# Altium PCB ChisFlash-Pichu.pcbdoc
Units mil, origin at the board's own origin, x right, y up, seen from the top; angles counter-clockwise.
Board outline 4828 x 2046.68 mil, 2 copper layers (Top Layer, Bottom Layer); 21 components, 58 nets, 251 pads, 209 vias.
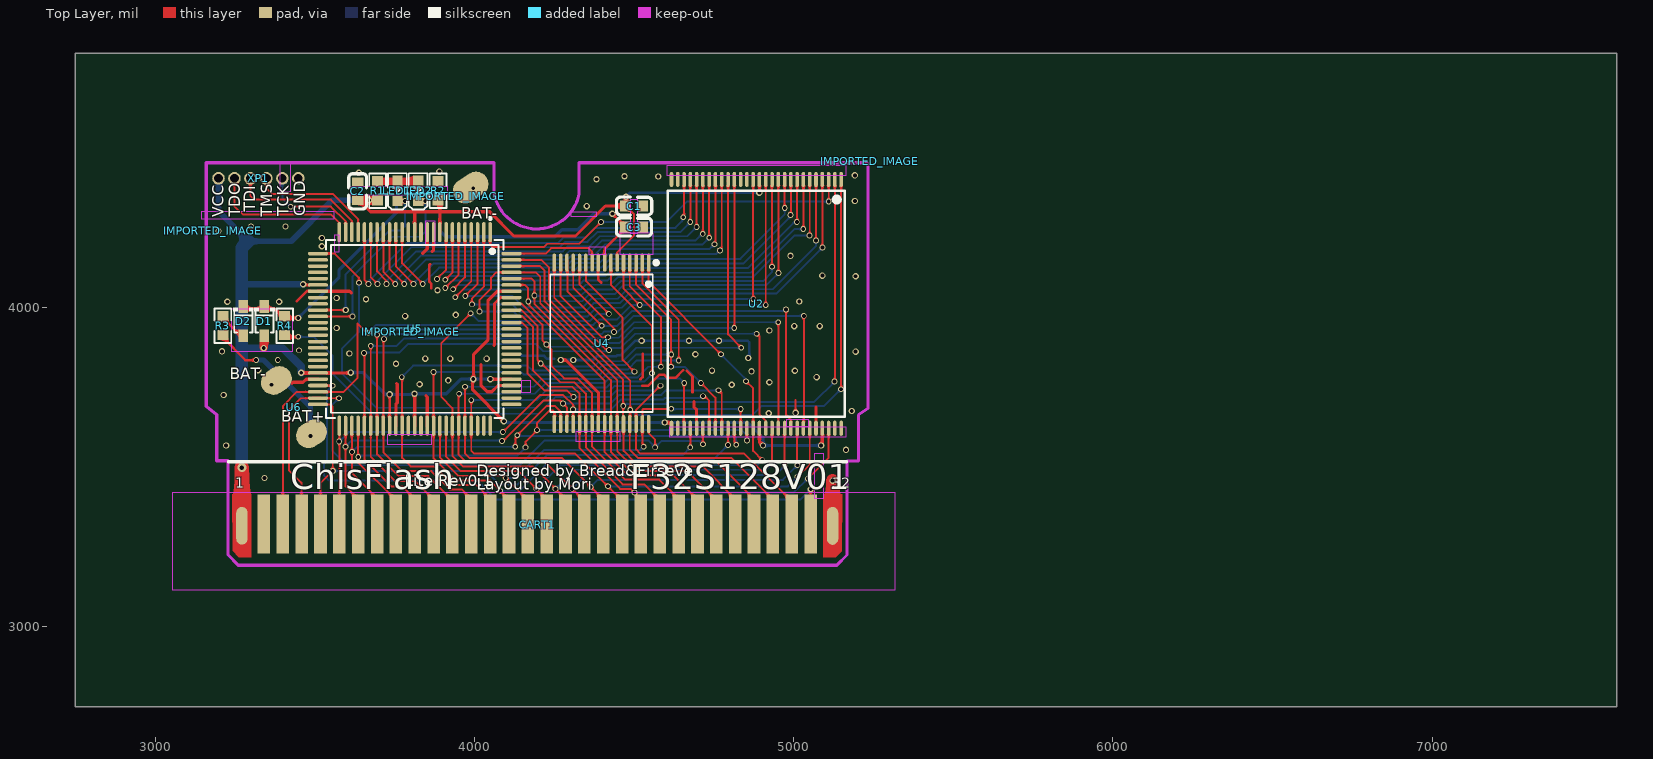
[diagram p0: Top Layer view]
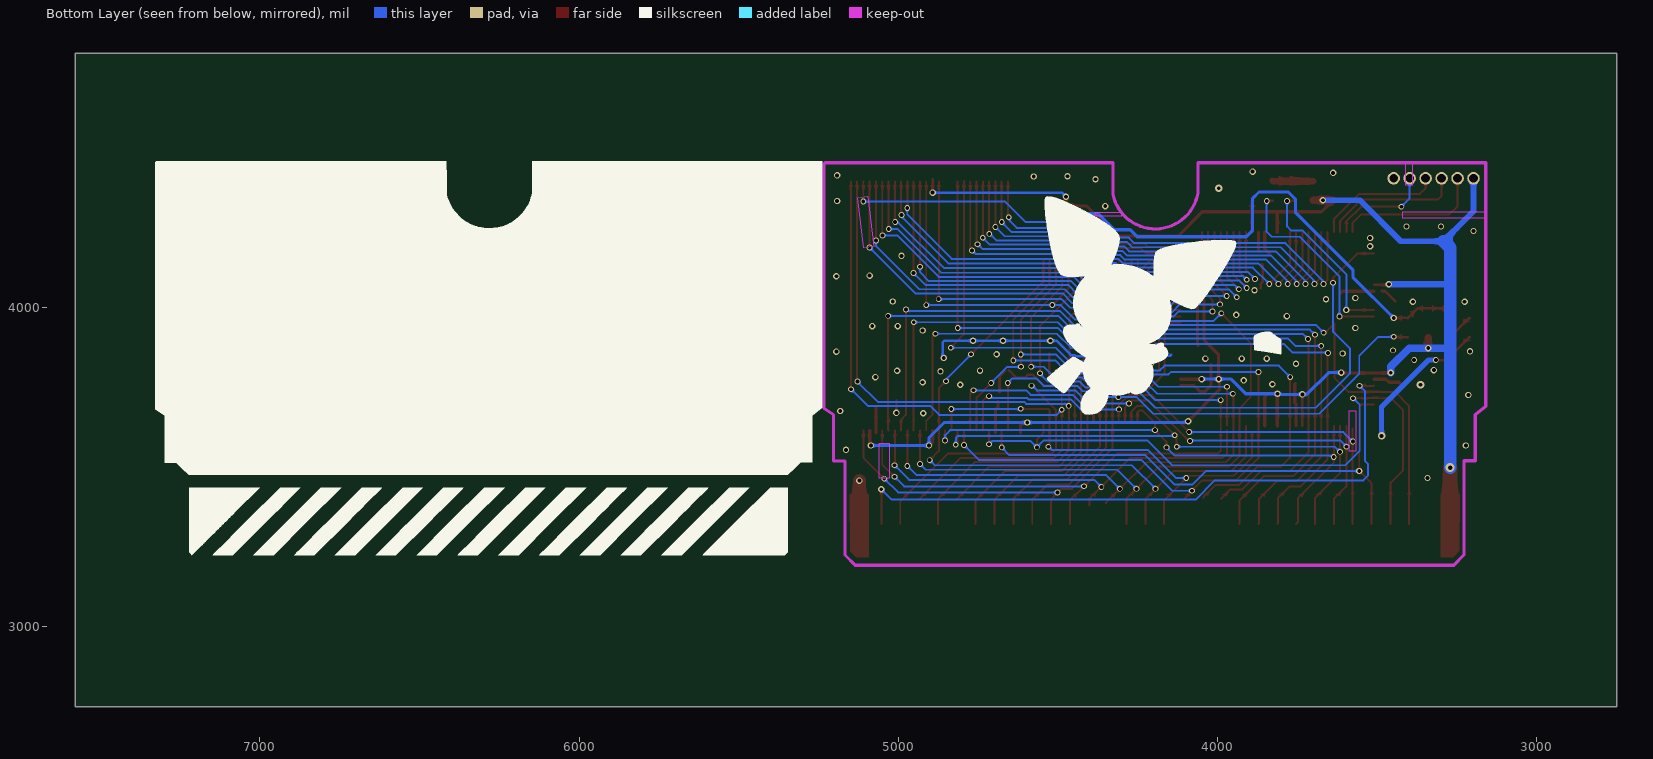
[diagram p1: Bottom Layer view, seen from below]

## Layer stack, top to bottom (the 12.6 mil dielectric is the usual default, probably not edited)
Top Layer: signal copper (thickness not stored)
Dielectric: dielectric 12.6, FR-4, Dk 4.8
Bottom Layer: signal copper (thickness not stored)

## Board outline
7578,2750 2750,2750 2750,4796.68 7578,4796.68

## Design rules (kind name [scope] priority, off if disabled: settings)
Clearance copperThickness1oz [All] p1: gap=7 ignorepadtopadclearanceinfootprint=FALSE except(6: Track-Track Track-SMDPad SMDPad-SMDPad Track-THPad SMDPad-THPad THPad-THPad Track-Via SMDPad-Via THPad-Via Via-Via Track-Fill SMDPad-Fill THPad-Fill Via-Fill Fill-Fill Track-Region SMDPad-Region THPad-Region Via-Region Fill-Region Region-Region Track-Poly SMDPad-Poly THPad-Poly Via-Poly Fill-Poly Region-Poly Poly-Poly Track-Text SMDPad-Text THPad-Text Via-Text Fill-Text Region-Text Poly-Text Text-Text SMDPad-Sheet THPad-Sheet Via-Sheet Fill-Sheet Region-Sheet Poly-Sheet Text-Sheet Track-Hole SMDPad-Hole THPad-Hole Via-Hole Fill-Hole Region-Hole Poly-Hole Text-Hole Sheet-Hole; 11.8: Track-Sheet)
Clearance copperThickness2oz [All] p1: gap=7 ignorepadtopadclearanceinfootprint=FALSE except(6: Track-Track Track-SMDPad SMDPad-SMDPad Track-THPad SMDPad-THPad THPad-THPad Track-Via SMDPad-Via THPad-Via Via-Via Track-Fill SMDPad-Fill THPad-Fill Via-Fill Fill-Fill Track-Region SMDPad-Region THPad-Region Via-Region Fill-Region Region-Region Track-Poly SMDPad-Poly THPad-Poly Via-Poly Fill-Poly Region-Poly Poly-Poly Track-Text SMDPad-Text THPad-Text Via-Text Fill-Text Region-Text Poly-Text Text-Text SMDPad-Sheet THPad-Sheet Via-Sheet Fill-Sheet Region-Sheet Poly-Sheet Text-Sheet Track-Hole SMDPad-Hole THPad-Hole Via-Hole Fill-Hole Region-Hole Poly-Hole Text-Hole Sheet-Hole; 11.8: Track-Sheet)
DiffPairsRouting differentialPair [All] p1: maxuncoupledlength=10 maxlimit=6 mostfreqgap=6 toplayer_minwidth=6 toplayer_prefwidth=10 toplayer_maxwidth=100 bottomlayer_minwidth=6 bottomlayer_prefwidth=10 bottomlayer_maxwidth=100
PasteMaskExpansion pasteMaskExpansion [All] p1:
PlaneConnect innerPlane [All] p1: planeconnectstyle=Relief reliefexpansion=20 reliefentries=4 reliefconductorwidth=10 reliefairgap=10
PolygonConnect copperRegion [All] p1: connectstyle=Direct reliefentries=4 reliefconductorwidth=10 polygonreliefangle="90 Angle" airgapwidth=10
RoutingVias viaSize [All] p1: viastyle="Through Hole" holewidth=12 minholewidth=12 maxholewidth=248 width=20 minwidth=16 maxwidth=393.7
SolderMaskExpansion solderMaskExpansion [All] p1: useseparateexpansions=TRUE expansion=2 expansionbottom=2
Width copperThickness1oz [All] p1: maxlimit=100 minlimit=6 preferedwidth=8
Width copperThickness2oz [All] p1: maxlimit=100 minlimit=6 preferedwidth=10

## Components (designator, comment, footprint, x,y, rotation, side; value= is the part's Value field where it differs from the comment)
C1 "CAP_0603" C0603 4500,4318.68 r180 top
C2 "CAP_0603" C0603 3633.94,4364.68 r270 top
C3 "CGA0603X7R104K500JT" C0603 4500,4252.68 r0 top
CART1 "GBACartridge" GBACartridge 4195.7,3905.83 r0 top
D1 "1N4148WS_C917117" SOD-323_L1.8-W1.3-LS2.5-RD 3342,3957.89 r270 top
D2 "1N4148WS_C917117" SOD-323_L1.8-W1.3-LS2.5-RD 3276,3957.89 r270 top
IMPORTED_IMAGE "IMPORTED_IMAGE" IMPORTED_IMAGE 3180,4240.68 r0 top
IMPORTED_IMAGE "IMPORTED_IMAGE" IMPORTED_IMAGE 3942,4348.68 r0 top
IMPORTED_IMAGE "IMPORTED_IMAGE" IMPORTED_IMAGE 3800,3924.68 r0 top
IMPORTED_IMAGE "IMPORTED_IMAGE" IMPORTED_IMAGE 5238,4458.68 r0 top
LED1 "NCD0603B1" LED0603-RD 3758.38,4366.68 r90 top
LED2 "NCD0603G1" LED0603-RD 3823.78,4366.68 r90 top
R1 "0603WAF1001T5E" R0603 3696.28,4366.68 r270 top
R2 "0603WAF1003T5E" R0603 3885.94,4366.68 r90 top
R3 "0603WAF1002T5E" R0603 3212,3943.84 r90 top
R4 "0603WAF1002T5E" R0603 3405.35,3943.84 r90 top
U2 "S29GL256S10TFI010" TSOP-56_L18.4-W14.0-P0.50-LS20.0-TL 4883,4012.43 r270 top
U4 "={Manufacturer Part}" STSOP-32_L8.0-W11.8-P0.50-LS13.4-TL 4398,3888.51 r270 top
U5 "EPM240T100C5N" TQFP-100_L14.0-W14.0-P0.50-LS16.0-BL 3812.79,3933.68 r180 top
U6 "+电池-" 电池 3379.43,3772.2 r303.35 top
XP1 "jtag" HDR-TH_6P-P1.27-V-M-1 3323,4405.68 r0 top

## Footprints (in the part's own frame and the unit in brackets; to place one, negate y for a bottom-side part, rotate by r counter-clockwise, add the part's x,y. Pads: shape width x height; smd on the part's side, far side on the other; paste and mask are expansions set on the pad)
C0603 [mm]
  rect 0.8x0.9 smd: 1(-0.7,0) 2(0.7,0)
  silkscreen extent -1.41,-0.71 1.39,0.72
GBACartridge [mm]
  oval 0.905x2.997 smd: 1(-23.479,-14.958)
  rect 1x4.691 smd: 2(-21.724,-14.805) 3(-20.224,-14.805) 4(-18.724,-14.805) 5(-17.224,-14.805) 6(-15.724,-14.805) 7(-14.224,-14.805) 8(-12.724,-14.805) 9(-11.224,-14.805) 10(-9.724,-14.805) 11(-8.224,-14.805) 12(-6.724,-14.805) 13(-5.224,-14.805) 14(-3.724,-14.805) 15(-2.224,-14.805) 16(-0.724,-14.805) 17(0.776,-14.805) 18(2.276,-14.805) 19(3.776,-14.805) 20(5.276,-14.805) 21(6.776,-14.805) 22(8.276,-14.805) 23(9.776,-14.805) 24(11.276,-14.805) 25(12.776,-14.805) 26(14.276,-14.805) 27(15.776,-14.805) 28(17.276,-14.805) 29(18.776,-14.805) 30(20.276,-14.805) 31(21.776,-14.805)
  oval 0.904x3.008 smd: 32(23.529,-14.966)
  Top Layer region: 22.775,-17.473 22.782,-12.46 24.282,-12.46 24.275,-16.973 23.775,-17.473
  Top Layer region: -22.733,-12.46 -22.725,-17.456 -23.725,-17.456 -24.224,-16.956 -24.233,-12.46
HDR-TH_6P-P1.27-V-M-1 [mm]
  round 1 hole 0.7: 1(-3.175,0) 2(-1.905,0) 3(-0.635,0) 4(0.635,0) 5(1.905,0) 6(3.175,0)
IMPORTED_IMAGE [mil]
LED0603-RD [mm]
  rect 0.8x0.8 smd: 1(-0.799,0) 2(0.799,0)
  silkscreen extent -1.49,-0.75 1.39,0.76
R0603 [mil]
  rect 31.75x34.02 smd: 1(-29.66,0) 2(29.66,0)
  silkscreen extent -55,-26 55,26
SOD-323_L1.8-W1.3-LS2.5-RD [mm]
  rect 1x0.75 smd: 1(-1.173,0) 2(1.173,0)
  silkscreen extent -1.08,-0.8 0.9,0.8
STSOP-32_L8.0-W11.8-P0.50-LS13.4-TL [mm]
  oval 1.44x0.28 smd: 1(-6.42,3.75) 2(-6.42,3.25) 3(-6.42,2.75) 4(-6.42,2.25) 5(-6.42,1.75) 6(-6.42,1.25) 7(-6.42,0.75) 8(-6.42,0.25) 9(-6.42,-0.25) 10(-6.42,-0.75) 11(-6.42,-1.25) 12(-6.42,-1.75) 13(-6.42,-2.25) 14(-6.42,-2.75) 15(-6.42,-3.25) 16(-6.42,-3.75) 17(6.42,-3.75) 18(6.42,-3.25) 19(6.42,-2.75) 20(6.42,-2.25) 21(6.42,-1.75) 22(6.42,-1.25) 23(6.42,-0.75) 24(6.42,-0.25) 25(6.42,0.25) 26(6.42,0.75) 27(6.42,1.25) 28(6.42,1.75) 29(6.42,2.25) 30(6.42,2.75) 31(6.42,3.25) 32(6.42,3.75)
  silkscreen extent -6.57,-4.08 5.47,4.49
TQFP-100_L14.0-W14.0-P0.50-LS16.0-BL [mm]
  oval 0.28x1.6 smd: 1(-6,-7.7) 2(-5.5,-7.7) 3(-5,-7.7) 4(-4.5,-7.7) 5(-4,-7.7) 6(-3.5,-7.7) 7(-3,-7.7) 8(-2.5,-7.7) 9(-2,-7.7) 10(-1.5,-7.7) 11(-1,-7.7) 12(-0.5,-7.7) 13(0,-7.7) 14(0.5,-7.7) 15(1,-7.7) 16(1.5,-7.7) 17(2,-7.7) 18(2.5,-7.7) 19(3,-7.7) 20(3.5,-7.7) 21(4,-7.7) 22(4.5,-7.7) 23(5,-7.7) 24(5.5,-7.7) 25(6,-7.7) 51(6,7.7) 52(5.5,7.7) 53(5,7.7) 54(4.5,7.7) 55(4,7.7) 56(3.5,7.7) 57(3,7.7) 58(2.5,7.7) 59(2,7.7) 60(1.5,7.7) 61(1,7.7) 62(0.5,7.7) 63(0,7.7) 64(-0.5,7.7) 65(-1,7.7) 66(-1.5,7.7) 67(-2,7.7) 68(-2.5,7.7) 69(-3,7.7) 70(-3.5,7.7) 71(-4,7.7) 72(-4.5,7.7) 73(-5,7.7) 74(-5.5,7.7) 75(-6,7.7)
  oval 1.6x0.28 smd: 26(7.7,-6) 27(7.7,-5.5) 28(7.7,-5) 29(7.7,-4.5) 30(7.7,-4) 31(7.7,-3.5) 32(7.7,-3) 33(7.7,-2.5) 34(7.7,-2) 35(7.7,-1.5) 36(7.7,-1) 37(7.7,-0.5) 38(7.7,0) 39(7.7,0.5) 40(7.7,1) 41(7.7,1.5) 42(7.7,2) 43(7.7,2.5) 44(7.7,3) 45(7.7,3.5) 46(7.7,4) 47(7.7,4.5) 48(7.7,5) 49(7.7,5.5) 50(7.7,6) 76(-7.7,6) 77(-7.7,5.5) 78(-7.7,5) 79(-7.7,4.5) 80(-7.7,4) 81(-7.7,3.5) 82(-7.7,3) 83(-7.7,2.5) 84(-7.7,2) 85(-7.7,1.5) 86(-7.7,1) 87(-7.7,0.5) 88(-7.7,0) 89(-7.7,-0.5) 90(-7.7,-1) 91(-7.7,-1.5) 92(-7.7,-2) 93(-7.7,-2.5) 94(-7.7,-3) 95(-7.7,-3.5) 96(-7.7,-4) 97(-7.7,-4.5) 98(-7.7,-5) 99(-7.7,-5.5) 100(-7.7,-6)
  silkscreen extent -7.08,-8.9 7.08,7.08
TSOP-56_L18.4-W14.0-P0.50-LS20.0-TL [mil]
  oval 47.2x11 smd: 1(-389.8,265.8) 2(-389.8,246.1) 3(-389.8,226.4) 4(-389.8,206.7) 5(-389.8,187) 6(-389.8,167.3) 7(-389.8,147.6) 8(-389.8,128) 9(-389.8,108.3) 10(-389.8,88.6) 11(-389.8,68.9) 12(-389.8,49.2) 13(-389.8,29.5) 14(-389.8,9.8) 15(-389.8,-9.8) 16(-389.8,-29.5) 17(-389.8,-49.2) 18(-389.8,-68.9) 19(-389.8,-88.6) 20(-389.8,-108.3) 21(-389.8,-127.9) 22(-389.8,-147.6) 23(-389.8,-167.3) 24(-389.8,-187) 25(-389.8,-206.7) 26(-389.8,-226.4) 27(-389.8,-246.1) 28(-389.8,-265.7) 29(389.8,-265.7) 30(389.8,-246.1) 31(389.8,-226.4) 32(389.8,-206.7) 33(389.8,-187) 34(389.8,-167.3) 35(389.8,-147.6) 36(389.8,-127.9) 37(389.8,-108.3) 38(389.8,-88.6) 39(389.8,-68.9) 40(389.8,-49.2) 41(389.8,-29.5) 42(389.8,-9.8) 43(389.8,9.8) 44(389.8,29.5) 45(389.8,49.2) 46(389.8,68.9) 47(389.8,88.6) 48(389.8,108.3) 49(389.8,128) 50(389.8,147.6) 51(389.8,167.3) 52(389.8,187) 53(389.8,206.7) 54(389.8,226.4) 55(389.8,246.1) 56(389.8,265.8)
  silkscreen extent -354,-278 354,278
电池 [mm]
  oval 2x2.54 smd: 1(0,0) 2(5.08,0)

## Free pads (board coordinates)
  oval 118.11x78.74 smd rot 33.35: 2(3988,4376.68)

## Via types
v1: diameter 18, hole 12, Top Layer to Bottom Layer, 125 vias
v2: diameter 20, hole 12, Top Layer to Bottom Layer, 80 vias
v3: diameter 24, hole 12, Top Layer to Bottom Layer, 3 vias
v4: diameter 28, hole 14, Top Layer to Bottom Layer, 1 vias

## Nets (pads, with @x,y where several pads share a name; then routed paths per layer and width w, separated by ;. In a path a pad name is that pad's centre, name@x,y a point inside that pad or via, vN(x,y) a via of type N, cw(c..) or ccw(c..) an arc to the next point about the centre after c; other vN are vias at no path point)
$1N77583: LED1.2 LED2.2 R1.1 | length 128.2
  Top Layer w20: R1.1@3700.28,4396.34 3825.96,4396.34 LED2.2@3827.78,4398.15
$1N81263: D2.2 R3.2 | length 89.6
  Top Layer w8: R3.2@3210,3967.5 3212.23,3967.5 D2.2@3274,3905.73
$1N81264: R3.1 U6.2 | length 458.1
  Top Layer w8: R3.1@3210,3908.18 3282.53,3835.65 3314.97,3835.65 v1(3316,3836.68)
  Bottom Layer w16: v1(3316,3836.68) 3338.63,3836.68 3486,3689.3 v3(3486,3598.68)
A16: CART1.22 U2.54 U4.21 U5.90 | length 1638.8
  Top Layer w6: U5.90 4149.63,3973.05 4184,3938.68 4184,3802.68 4234,3752.68 4306.37,3752.68 4329.1,3729.94 4329.1,3640.91 4329.1,3559.86 4456.29,3432.68 4490.2,3432.68 v1(4501.46,3421.42) 4501.46,3420.58 4521.51,3400.53 CART1.22 ; v1(5044,3464.68) 5109.4,3530.08 U2.54@5109.4,3615.88
  Bottom Layer w6: v1(4501.46,3421.42) 5000.74,3421.42 v1(5044,3464.68)
A17: CART1.23 U2.19 U4.22 U5.91 | length 2146
  Top Layer w6: U5.91 4147.94,3992.74 4198,3942.68 4198,3835.62 v1(4207.8,3825.82) 4208.94,3825.82 4268.08,3766.68 4313.24,3766.68 4348.79,3731.12 4348.79,3636.91 4348.79,3562.31 4464.19,3446.91 4532.49,3446.91 4580.56,3398.84 CART1.23 ; U2.19@4792,4397.88 4794.33,4395.55 4794.33,3916.35 v1(4836,3874.68)
  Bottom Layer w6: v1(4207.8,3825.82) 4217.47,3816.15 4374.89,3816.15 4391.13,3832.39 4464,3832.39 4506.28,3874.68 v1(4836,3874.68)
A18: CART1.24 U2.18 U4.23 U5.92 | length 2085.9
  Top Layer w6: U5.92 4116.2,4012.68 4148,4012.68 4213.06,3947.61 4213.06,3897.61 v1(4226,3884.68) 4242,3868.68 4242,3817.5 4280.82,3778.68 4321.41,3778.68 4368.47,3731.61 4368.47,3636.91 4368.47,3565.14 4472.15,3461.46 4579.21,3461.46 4639.62,3401.06 CART1.24 ; v1(4814,3936.68) 4814.1,3936.78 U2.18@4814.1,4395.48
  Bottom Layer w6: v1(4226,3884.68) 4232.64,3878.04 4401.34,3878.04 4412.82,3889.52 4454.19,3889.52 4501.35,3936.68 v1(4814,3936.68)
A19: CART1.25 U2.11 U4.25 U5.95 | length 2206.2
  Top Layer w6: U5.95 4157.32,4071.48 4168.23,4060.57 v1(4168.23,4019.71) 4168.23,4011.73 4407.84,3772.11 U4.25 4407.84,3547.43 4480.12,3475.15 4623.53,3475.15 4698.67,3400 CART1.25 ; U2.11@4951.9,4395.48 4952.23,4395.15 v1(4952.23,4108.93)
  Bottom Layer w6: v1(4168.23,4019.71) 4168.9,4020.38 4337.05,4020.38 4359.61,4042.95 4439.54,4042.95 4467.99,4071.4 4915.37,4071.4 4952.23,4108.25 v1(4952.23,4108.93)
A20: CART1.26 U2.12 U4.26 U5.96 | length 2235.8
  Top Layer w6: U5.96 4179.52,4091.16 4187.66,4083.01 v1(4187.66,4038.78) 4187.66,4013.01 4427.53,3773.14 U4.26 4427.53,3548.56 4487.25,3488.84 4665.84,3488.84 4757.73,3396.95 CART1.26 ; v1(4932,4128.68) 4932,4395.28 U2.12@4932.2,4395.48
  Bottom Layer w6: v1(4187.66,4038.78) 4189.24,4037.2 4333.32,4037.2 4353.32,4057.21 4432.29,4057.21 4458.51,4083.43 4903.97,4083.43 4932,4111.46 v1(4932,4128.68)
A21: CART1.27 U2.15 U4.27 U5.97 | length 2624.1
  Top Layer w6: v1(4016,3988.68) 4016,4024.68 4052,4060.68 4052,4094.68 4068.17,4110.85 U5.97 4191.83,4110.85 4206,4096.68 4206,4013.88 4447.21,3772.67 4447.21,3636.91 4447.21,3550.71 4495.1,3502.82 4714.51,3502.82 CART1.27@4819.16,3398.17 ; U2.15@4873.2,4395.48 4873.2,4027.63 v1(4873.75,4027.09)
  Bottom Layer w6: v1(4016,3988.68) 4122,3988.68 4138.21,3972.46 4353.5,3972.46 4381.21,4000.17 4461.35,4000.17 4488.22,4027.05 v1@4873.71,4027.05
A22: CART1.28 U2.2 U4.28 U5.98 | length 2647.1
  Top Layer w6: U5.98 4206.15,4130.53 4220,4116.68 4220,4020.13 4465.91,3774.22 4465.91,3692.68 4465.91,3641.9 4466.9,3640.91 4466.9,3551.64 4501.91,3516.64 4760.04,3516.64 4875.84,3400.84 CART1.28 ; v1(5128,3768.68) 5129.1,3769.78 U2.2@5129.1,4395.48
  Bottom Layer w6: v1(4466,3692.68) 4472.23,3698.9 4599.69,3698.9 4605.69,3704.9 5064.23,3704.9 v1(5128,3768.68)
A23: CART1.29 U2.1 U4.29 U5.99 | length 2668.3
  Top Layer w6: U5.99 4208.46,4150.22 4234,4124.68 4234,4025.88 4488,3771.88 v1(4488,3680.68) 4488,3642.33 4486.58,3640.91 4486.58,3554.64 4511.73,3529.49 4805.18,3529.49 CART1.29@4935.25,3399.42 ; v1(5148,3744.68) 5148.8,3745.48 U2.1@5148.8,4395.48
  Bottom Layer w6: v1(4488,3680.68) 4504,3664.68 4872,3664.68 4899.73,3692.4 5095.73,3692.4 v1(5148,3744.68)
AD0: CART1.6 U2.35 U4.20 U5.51 | length 1701.7
  Top Layer w6: CART1.6 U5.51@3576.63,3622.53 ; v1(4088.98,3610.6) 4205.05,3726.68 4278.06,3726.68 4308.86,3695.87 v1(4308.86,3681.81) 4309.42,3681.25 U4.20@4309.42,3642.91 ; v1(4716.26,3723.12) 4721.56,3723.12 4735.4,3709.28 U2.35@4735.4,3615.88
  Bottom Layer w6: v1(3576,3580.68) 3605.58,3610.26 4088.63,3610.26 v1(4088.98,3610.6) ; v1(4308.86,3681.81) 4429.05,3681.81 4460.25,3713.01 4592.3,3713.01 4596.55,3717.4 4710.54,3717.4 v1(4716.26,3723.12)
AD1: CART1.7 U2.37 U4.19 U5.52 | length 1768.2
  Top Layer w6: U5.52@3596.27,3630.5 3596,3630.23 v1(3596,3564.68) 3596,3440.68 3635.68,3401 CART1.7 ; v1(4086,3582.68) 4090,3582.68 4217.28,3709.96 4267.56,3709.96 v1(4277.09,3700.43) 4289.73,3687.79 U4.19@4289.73,3642.91 ; v1(4764.89,3741.46) 4774.7,3731.65 U2.37@4774.7,3615.88
  Bottom Layer w6: v1(3596,3564.68) 3616,3584.68 4084,3584.68 v1(4086,3582.68) ; v1(4277.09,3700.43) 4426.34,3700.43 4453.16,3727.25 4585.51,3727.25 4599.72,3741.46 v1(4764.89,3741.46)
AD2: CART1.8 U2.39 U4.18 U5.53 | length 1869.4
  Top Layer w6: U5.53 3615.94,3548.68 3615.94,3482.74 3694.74,3403.94 CART1.8 ; v1(4128,3564.68) 4128,3594.68 v1(4134,3600.68) 4226,3692.68 4251.49,3692.68 4270.05,3674.11 U4.18@4270.05,3642.91 ; U2.39@4814.1,3615.88 4814.1,3576.58 v1(4820,3570.68)
  Bottom Layer w6: v1(3616,3548.68) 3632,3564.68 v1(4128,3564.68) ; v1(4134,3600.68) 4136,3598.68 4814,3598.68 4820,3592.68 v1(4820,3570.68)
AD3: CART1.9 U2.41 U4.17 U5.54 | length 1802.2
  Top Layer w6: U5.54 3635.62,3533.06 v1(3636,3532.68) 3636,3514.68 3748,3402.68 3748,3328.73 CART1.9 ; v1(4160,3562.68) 4160,3580.68 v1(4196,3616.68) 4196,3639.05 4235.62,3678.68 4246,3678.68 4250.36,3674.31 U4.17@4250.36,3640.91 ; v1(4853.55,3584.51) U2.41@4853.55,3615.83
  Bottom Layer w6: v1(3636,3532.68) 3640,3536.68 4134,3536.68 v1(4160,3562.68) ; v1(4196,3616.68) 4838,3616.68 4853.55,3601.13 v1(4853.55,3584.51)
AD4: CART1.10 U2.44 U4.16 U5.55 | length 2566.3
  Top Layer w6: v1(3654,3858.68) 3655.31,3857.37 U5.55 3655.31,3524.98 3739.61,3440.68 3774,3440.68 3810,3404.68 3810,3325.79 CART1.10 ; U4.16@4250,4148.8 4250,4031.4 4413.37,3868.03 v1(4421.15,3868.03) ; v1(4884,3918.68) 4893.46,3909.22 4893.46,3665.22 4912.5,3646.18 U2.44@4912.5,3615.88
  Bottom Layer w6: v1(3654,3858.68) 3655,3859.68 3765,3859.68 3792,3886.68 4192.7,3886.68 4215.51,3863.87 4416.99,3863.87 v1(4421.15,3868.03) 4427.15,3874.03 4458.85,3874.03 4503.49,3918.68 v1(4884,3918.68)
AD5: CART1.11 U2.46 U4.15 U5.56 | length 2637.7
  Top Layer w6: v1(3675.18,3880.7) 3675.15,3630.7 U5.56 3674.99,3532.6 3751.1,3456.48 3815.07,3456.48 3870,3401.56 3870,3324.84 CART1.11 ; U4.15@4269.99,4148.39 4269.99,4036.56 4398.75,3907.8 v1(4418.1,3907.78) ; U2.46@4951.9,3615.88 4951.9,3845.07 4952,3845.16 v1(4952,3954.68)
  Bottom Layer w6: v1(3675.18,3880.7) 3756.1,3880.7 3778.73,3903.33 4413.64,3903.33 v1(4418.1,3907.78) 4419.67,3906.21 4451.78,3906.21 4500.25,3954.68 v1(4952,3954.68)
AD6: CART1.12 U2.48 U4.14 U5.57 | length 2696.8
  Top Layer w6: v1(3694.51,3915.47) 3694.68,3915.3 U5.57 3694.68,3540.96 3763.18,3472.46 3855.35,3472.46 3930.96,3396.85 CART1.12 ; U4.14@4288,4150.17 4292,4146.17 4292,4050.46 v1(4399,3943.46) ; v1(4976.34,3994.68) 4976.34,3664.34 4991.3,3649.38 U2.48@4991.3,3615.88
  Bottom Layer w6: v1(3694.51,3915.47) 3710.72,3931.68 4382.22,3931.68 4394,3943.46 v1(4399,3943.46) 4447.14,3943.46 4493.03,3989.35 4971.01,3989.35 v1(4976.34,3994.68)
AD7: CART1.13 U2.50 U4.13 U5.58 | length 2674.4
  Top Layer w6: v1(3716.53,3902.47) 3714.36,3900.3 U5.58 3714.36,3547.73 3773.84,3488.25 3865.03,3488.25 3922.02,3431.25 3959.77,3431.25 CART1.13@3989.02,3402 ; U4.13@4309.42,4148.43 4309.42,4062.72 4437.33,3934.82 v1(4437.33,3924.16) ; U2.50@5030.6,3615.88 5032,3617.28 v1(5032,3974.68)
  Bottom Layer w6: v1(3716.53,3902.47) 3731.9,3917.84 4398.75,3917.84 4407.15,3926.23 4435.26,3926.23 v1(4437.33,3924.16) 4448.91,3924.16 4499.42,3974.68 v1(5032,3974.68)
AD8: CART1.14 U2.36 U4.3 U5.61 | length 2124.6
  Top Layer w6: v1(3772,3782.68) 3773.42,3781.26 U5.61 3773.42,3529.67 3799.91,3503.18 3874.44,3503.18 3932.48,3445.14 4005.84,3445.14 4043.69,3407.29 CART1.14@4043.69,3404.56 ; U4.3@4506.27,4148.43 4506.27,4072.4 4616.36,3962.31 v1(4616.36,3853.99) 4615.66,3853.29 v1(4615.66,3815) ; v1(4709.23,3764.4) 4755.1,3718.54 U2.36@4755.1,3615.88
  Bottom Layer w6: v1(3772,3782.68) 3808,3818.68 4166,3818.68 4180.53,3804.15 4384.07,3804.15 4400.11,3820.19 4472.95,3820.19 4506.75,3853.99 v1(4616.36,3853.99) ; v1(4615.66,3815) 4658.64,3815 v1(4709.23,3764.4)
AD9: CART1.15 U2.38 U4.2 U5.66 | length 2526.7
  Top Layer w6: v1(3872,3798.68) 3871.84,3798.51 U5.66 3871.84,3528.29 3940.78,3459.35 4047.33,3459.35 v1(4080,3426.68) 4104.91,3401.77 CART1.15@4104.91,3400.65 ; U4.2@4526,4148.39 4526,4076.68 4640.08,3962.6 v1(4640.08,3835.14) ; v1(4794.12,3569.77) 4794.4,3570.05 U2.38@4794.4,3615.88
  Bottom Layer w6: v1(3872,3798.68) 4145.96,3798.68 4153.65,3790.99 4394.37,3790.99 4410.36,3806.98 4481.03,3806.98 4509.2,3835.14 v1(4640.08,3835.14) ; v1(4080,3426.68) 4142,3426.68 4238,3522.68 4747.03,3522.68 v1(4794.12,3569.77)
AD10: 
AD11: CART1.17 U2.42 U4.1 U5.68 | length 2061.2
  Top Layer w6: U5.68 3911.21,3533.78 3956.74,3488.25 4138.43,3488.25 v1(4194,3432.68) 4226.23,3400.44 CART1.17 ; U4.1@4545.64,4146.43 4545.64,4081.03 v1(4772,3854.68) ; v1(4850.68,3770.05) 4873.2,3747.53 U2.42 4873.2,3551.48 v1(4902,3522.68)
  Bottom Layer w6: v1(4194,3432.68) 4268,3506.68 4886,3506.68 v1(4902,3522.68) ; v1(4772,3854.68) 4850.68,3776 v1(4850.68,3770.05)
AD12: CART1.18 U2.45 U4.12 U5.69 | length 2458.3
  Top Layer w6: v1(3988,3982.68) 3930.9,3925.57 3930.9,3923.57 3896,3888.68 3896,3720.68 3930.9,3685.78 U5.69 3930.9,3537.03 3965.27,3502.65 4184.03,3502.65 v1(4254,3432.68) 4285.29,3401.39 CART1.18 ; U4.12@4329.1,4146.43 4329.1,4072.77 v1(4420.96,3980.91) ; v1(4932,3510.68) 4932.2,3510.88 U2.45@4932.2,3615.88
  Bottom Layer w6: v1(3988,3982.68) 4011.79,3958.89 4362.8,3958.89 4384.82,3980.91 v1(4420.96,3980.91) ; v1(4254,3432.68) 4314,3492.68 4914,3492.68 v1(4932,3510.68)
AD13: CART1.19 U2.47 U4.4 U5.70 | length 2500.7
  Top Layer w6: v1(3952,3730.68) 3950.58,3729.25 U5.70 3950.58,3539.83 3974.23,3516.17 4222.51,3516.17 v1(4306,3432.68) 4349.83,3388.85 CART1.19@4349.83,3386.95 ; U4.4@4486.58,4146.43 4486.58,4068.09 4583.92,3970.75 v1(4583.92,3815.33) ; U2.47@4971.6,3615.88 4971.6,3505.08 v1(4972,3504.68)
  Bottom Layer w6: v1(3952,3730.68) 4189.13,3730.68 4222.74,3764.29 4406.87,3764.29 4423.86,3781.27 4510.14,3781.27 4544.19,3815.33 v1(4583.92,3815.33) ; v1(4306,3432.68) 4350,3476.68 4944,3476.68 v1(4972,3504.68)
AD14: CART1.20 U2.49 U4.11 U5.71 | length 2450
  Top Layer w6: v1(3970,3752.68) 3970.27,3752.41 U5.71 ; U5.71@3970.74,3615.09 3970.74,3543.32 3984.41,3529.65 4273.03,3529.65 v1(4364,3438.68) 4401.24,3401.43 CART1.20@4401.24,3380.81 ; U4.11@4348.79,4146.43 4350,4145.23 4350,4083 4464,3969 4464,3837.04 v1(4501.13,3799.92) ; U2.49@5011,3615.88 5011,3507.68 v1(5012,3506.68)
  Bottom Layer w6: v1(3970,3752.68) 4185.84,3752.68 4210.35,3777.19 4400.28,3777.19 4416.56,3793.47 4494.68,3793.47 v1(4501.13,3799.92) ; v1(4364,3438.68) 4386,3460.68 4966,3460.68 v1(5012,3506.68)
AD15: CART1.21 U2.51 U4.7 U5.72 | length 2543.6
  Top Layer w6: v1@3989.95,3710.62 U5.72 3989.95,3552.31 3999.26,3543 4315.67,3543 v1(4418,3440.68) 4462.45,3396.22 CART1.21 ; U4.7@4427.53,4146.43 4427.53,4071.57 4556.25,3942.86 v1(4556.25,3794.93) ; v1(5012,3470.68) 5050.3,3508.98 U2.51@5050.3,3615.88
  Bottom Layer w6: v1(3990,3710.68) 4194.93,3710.68 4234.93,3750.68 4414,3750.68 4432.17,3768.85 4532.49,3768.85 4556.25,3792.61 v1(4556.25,3794.93) ; v1(4418,3440.68) 4982,3440.68 v1(5012,3470.68)
BK: U4.10 U5.100 | length 293.6
  Top Layer w6: U5.100 4223.22,4169.9 4240,4186.68 4358,4186.68 4368,4176.68 4368,4146.91 U4.10@4368.47,4146.43
FA0: U2.31 U5.26 | length 1792.5
  Top Layer w6: U5.26 3562.78,4169.9 3638,4094.68 v1(3638,4078.68) ; U2.31@4656.17,3615.45 4656.17,3763.5 v1(4657.01,3764.34)
  Bottom Layer w6: v1(3638,4078.68) 3638,3924.68 3584.54,3871.22 3584.54,3794.18 3692.04,3686.68 4195.69,3686.68 4247.61,3738.6 4421.92,3738.6 4438.85,3755.53 4544.96,3755.53 4568.11,3778.68 4642.68,3778.68 v1(4657.01,3764.34)
FA1: U2.26 U5.21 | length 1363
  Top Layer w6: U5.21 3655.31,4087.37 v1(3668,4074.68) ; v1(4654.18,4283.56) 4656.6,4285.98 U2.26@4656.6,4395.48
  Bottom Layer w6: v1(3668,4074.68) 3668,4083.16 3787.39,4202.55 4260.44,4202.55 4277.54,4219.65 4346.43,4219.65 4376.99,4250.21 4629.32,4250.21 4654.18,4275.07 v1(4654.18,4283.56)
FA2: U2.25 U5.20 | length 1363.1
  Top Layer w6: U5.20 3674.99,4095.69 v1(3696,4074.68) ; v1(4675.86,4268.48) 4676.3,4268.92 U2.25@4676.3,4395.48
  Bottom Layer w6: v1(3696,4074.68) 3696,4083.16 3802.39,4189.55 4267.31,4189.55 4284.08,4206.32 4353.99,4206.32 4384.75,4237.08 4644.29,4237.08 4675.69,4268.48 v1(4675.86,4268.48)
FA3: U2.24 U5.19 | length 1367.4
  Top Layer w6: U5.19 3694.68,4114 3724,4084.68 v1(3724,4074.68) ; v1(4696.01,4253.3) U2.24@4696,4395.48
  Bottom Layer w6: v1(3724,4074.68) 3724,4083.16 3817.44,4176.6 4276.94,4176.6 4292.41,4192.08 4360.46,4192.08 4392.44,4224.06 4666.71,4224.06 v1(4696.01,4253.3)
FA4: U2.23 U5.18 | length 1374.9
  Top Layer w6: U5.18 3714.36,4112.32 v1(3752,4074.68) ; v1(4714.96,4231.6) 4715.7,4232.33 U2.23@4715.7,4395.48
  Bottom Layer w6: v1(3752,4074.68) 3752,4083.16 3832.12,4163.28 4283.52,4163.28 4298.76,4178.52 4367.58,4178.52 4400.24,4211.19 4692.78,4211.19 4713.19,4231.6 v1(4714.96,4231.6)
FA5: U2.22 U5.17 | length 1378
  Top Layer w6: U5.17 3734.05,4120.63 v1(3780,4074.68) ; U2.22@4735.4,4395.48 4735.4,4219.97 v1(4735.73,4219.64)
  Bottom Layer w6: v1(3780,4074.68) 3780,4083.29 3847.89,4151.18 4290.29,4151.18 4304.11,4165 4375.19,4165 4408.06,4197.86 4713.96,4197.86 v1(4735.73,4219.64)
FA6: U2.21 U5.16 | length 1378.4
  Top Layer w6: U5.16 3753.73,4129.63 v1(3808.68,4074.68) ; v1(4752.26,4199.05) 4755.1,4201.89 U2.21@4755.1,4395.48
  Bottom Layer w6: v1(3808.68,4074.68) 3808.68,4075.94 3871.71,4138.97 4297.61,4138.97 4311.58,4152.94 4383.46,4152.94 4415.31,4184.79 4736.99,4184.79 4751.25,4199.05 v1(4752.26,4199.05)
FA7: U2.20 U5.15 | length 1382
  Top Layer w6: U5.15 3773.42,4139.12 v1(3837.86,4074.68) ; v1(4769.05,4179.4) 4774.7,4185.05 U2.20@4774.7,4395.48
  Bottom Layer w6: v1(3837.86,4074.68) 3837.86,4074.89 3889.06,4126.09 4304.05,4126.09 4318,4140.04 4391.52,4140.04 4419.4,4167.92 4757.58,4167.92 v1(4769.05,4179.4)
FA8: U2.10 U5.8 | length 1435
  Top Layer w6: v1(3882.52,4090.25) 3911.21,4118.94 U5.8 ; U2.10@4971.6,4395.48 4971.6,4313.08 v1(4972,4312.68)
  Bottom Layer w6: v1(3882.52,4090.25) 3904.71,4112.44 4309.82,4112.44 4324.12,4126.75 4398.26,4126.75 4424.99,4153.47 4833.16,4153.47 4972,4292.31 v1(4972,4312.68)
FA9: U2.9 U5.7 | length 1431.9
  Top Layer w6: v1(3908.48,4087.95) 3930.9,4110.37 U5.7 ; v1(4990,4290.68) 4991.3,4291.98 U2.9@4991.3,4395.48
  Bottom Layer w6: v1(3908.48,4087.95) 3919.85,4099.32 4317.34,4099.32 4330.74,4112.72 4404.14,4112.72 4430.26,4138.84 4843.06,4138.84 4990,4285.78 v1(4990,4290.68)
FA10: U2.8 U5.6 | length 1506.3
  Top Layer w6: v1(3908.67,4062.02) 3950.58,4103.93 U5.6 ; v1(5010,4268.68) 5011,4269.68 U2.8@5011,4395.48
  Bottom Layer w6: v1(3908.67,4062.02) 3931.59,4084.94 4322.88,4084.94 4337.79,4099.85 4411.38,4099.85 4436.4,4124.87 4857.71,4124.87 5001.51,4268.68 v1(5010,4268.68)
FA11: U2.7 U5.5 | length 1518.4
  Top Layer w6: v1(3933.15,4057.93) 3970.27,4095.05 U5.5 ; v1(5030,4246.68) 5030.6,4247.28 U2.7@5030.6,4395.48
  Bottom Layer w6: v1(3933.15,4057.93) 3947.24,4072.02 4329.05,4072.02 4342.93,4085.9 4417.26,4085.9 4441.21,4109.86 4864.92,4109.86 5001.74,4246.68 v1(5030,4246.68)
FA12: U2.6 U5.4 | length 1583.9
  Top Layer w6: v1(3939.74,4033.1) 3989.95,4083.3 U5.4 ; v1(5050,4226.68) 5050.3,4226.98 U2.6@5050.3,4395.48
  Bottom Layer w6: v1(3939.74,4033.1) 3963.76,4057.12 4333.4,4057.12 4348.36,4072.08 4425.6,4072.08 4450.16,4096.64 4873.68,4096.64 5003.71,4226.68 v1(5050,4226.68)
FA13: U2.5 U5.3 | length 1612
  Top Layer w6: v1(3970.94,4037.09) 4009.64,4075.78 U5.3 ; v1(5070,4210.68) U2.5@5070,4395.48
  Bottom Layer w6: v1(3970.94,4037.09) 4117.59,4037.09 4154.06,4000.62 4338.03,4000.62 4365.75,4028.34 4448.18,4028.34 4477.87,4058.03 4934.87,4058.03 5070,4193.16 v1(5070,4210.68)
FA14: U2.4 U5.2 | length 1640.4
  Top Layer w6: v1(3992,4010.68) 3992,4028.68 4029.32,4065.99 U5.2 ; U2.4@5089.7,4395.48 5090,4395.18 v1(5090,4188.68)
  Bottom Layer w6: v1(3992,4010.68) 4118,4010.68 4142.31,3986.36 4345.5,3986.36 4373.56,4014.42 4454.42,4014.42 4485.08,4045.09 4946.41,4045.09 v1(5090,4188.68)
FA15: U2.3 U5.1 | length 1224.9
  Top Layer w6: U5.1 4049.01,4197.67 4056,4190.68 4218,4190.68 4228,4200.68 4328.52,4200.68 v1(4396.73,4268.88) ; U2.3@5109.4,4395.48 5110,4394.88 v1(5110,4332.68)
  Bottom Layer w6: v1(4396.73,4268.88) 4601.99,4268.88 4665.79,4332.68 v1(5110,4332.68)
GND: C1.1 C2.1 C3.2 CART1.32 pad.2 R2.2 U2.33 U2.52 U4.9 U4.24 U5.10 U5.11 U5.32 U5.46 U5.60 U5.65 U5.79 U5.93 U6.1 XP1.6 | length 2819.2
  Top Layer w6: v2(5006,3670.79) 5006,3710.68
  Top Layer w8: 3443.45,4020.61 3475.48,4052.64 U5.32@3485.35,4052.64 ; 3860.63,4136.02 3858.6,4134 3858.6,4081.66 3864.45,4075.8 3864.45,4060.83 ; U4.9@4387.51,4121.51 4387.51,4088.22 4396.58,4079.15 ; 4520.2,3776.44 4526.84,3783.08 4526.84,3856.25 ; 4525.57,3755.2 4544.32,3755.2 4579.94,3790.82 4593.28,3790.82 4603.92,3780.18 4629.75,3780.18 4654.06,3804.5 ; 4665.46,3802.11 4683.02,3784.55 4683.02,3735.93
  Top Layer w10: 3428,3762.68 3431.78,3766.46 3462.86,3766.46 3472.6,3776.2 U5.46 ; U5.32 3608.89,4051.79 3614,4046.68 ; U5.60 3753.73,3698.4 3758,3702.68 3758,3760.68 3756,3762.68 ; 3838,4170.68 3852.16,4184.83 U5.11 ; 3848,3724.68 3852.16,3720.52 U5.65 ; 3868,4176.68 3871.84,4180.51 U5.10 ; 4020,3822.68 4020,3756.68 4040,3736.68 4054,3736.68 4073.84,3756.52 U5.79 ; 4060.77,3881.44 4062.79,3883.46 4062.79,4013.47 4081.43,4032.11 U5.93 ; v2(4270.53,3836.37) 4286.31,3836.37 4388.16,3734.51 U4.24@4388.16,3640.91 ; 4687.49,3705.53 4687.49,3689.19 4696,3680.68 4696,3631.88 U2.33@4696,3607.88 ; U2.52@5070,3607.88 5070,3631.88 5070,3688.68
  Top Layer w40: CART1.32 v2(5122.03,3458.68)
  Bottom Layer w8: 4145.12,3853.42 4149.29,3849.25 4218.08,3849.25 4227.4,3839.94 4249.59,3839.94 ; v2(4270.53,3836.37) v2(4309.52,3836.37) 4372.05,3836.37 4383.77,3848.09 4443.81,3848.09 4447.28,3851.56 4459.61,3851.56 4504.9,3896.85 v2(4523.49,3896.85) 4671.83,3896.85 v2(4672,3896.68) v2(4766,3896.68) 4855.42,3896.68 4861.53,3890.57 4861.53,3846.21 v2(4858,3842.68)
  other v1: 3384,3836.68 3450,3866.68
  other v2: 3342,3466.68 5164,3554.68 3222,3568.68 4922,3669.75 5182,3676.68 3214,3726.68 4806,3758.68 3828,3760.68 4924,3766.68 3918,3772.68 5072,3782.68 4868,3800.68 4744.09,3803.02 5004,3802.68 3322,3804.68 3754,3824.68 3846,3840.68 3924,3840.68 4038,3840.68 4692,3854.68 3608,3856.68 3209.13,3863.26 5194,3862.68 4924,3928.68 3568,3936.68 5002,3942.68 5082,3942.68 3782.77,3973.75 3941.57,3977.81 3226,4018.68 3388,4018.68 5017.45,4019.64 3660,4026.68 3568,4030.68 3884,4054.68 5194,4098.68 5090,4100.68 4990,4162.68 3522,4192.68 3522,4218.68 3198,4240.68 3300,4254.68 3408,4254.68 4352,4318.68 5192,4334.68 4382.47,4402.56 4575.58,4411.21 4469.89,4412.36 5192,4414.68 3638,4422.68 3890,4426.68
  other v3: 3364,3758.68 3996,4374.68
LED1: LED1.1 U5.35 | length 546.4
  Top Layer w6: U5.35 3509.89,3992.99 v2@3596.39,3992.99
  Top Layer w8: LED1.1@3762.38,4335.2 3762.9,4334.68 v1(3782,4334.68)
  Bottom Layer w6: v2(3596.45,3992.93) 3596.45,4105.13 3734,4242.68 3770,4242.68 3782,4254.68 v1(3782,4334.68)
LED2: LED2.1 U5.36 | length 634.9
  Top Layer w6: U5.36 3617.63,3973.05 v2(3618,3972.68)
  Top Layer w8: LED2.1@3827.78,4335.2 3828.3,4334.68 v1(3846,4334.68)
  Bottom Layer w6: v2(3618,3972.68) 3618,4098.68 3742,4222.68 3830,4222.68 3846,4238.68 v1(3846,4334.68)
REQ: CART1.31 U5.47 | length 2017.5
  Top Layer w6: U5.47 3510.65,3755.5 v1(3555.19,3755.5) ; CART1.31 5053,3430.6 v2(5053.79,3431.39)
  Bottom Layer w6: v1(3555.19,3755.5) 3537.93,3738.25 3537.93,3519.43 3528,3509.5 3528,3474.68 3543.23,3459.45 4008.36,3459.45 4068.95,3398.86 5021.26,3398.86 v2(5053.79,3431.39)
TCK: U5.24 XP1.5 | length 324.8
  Top Layer w6: v1(3424,4316.68) 3550,4316.68 3596.25,4270.43 U5.24
  Bottom Layer w6: XP1.5 3398,4342.68 v1(3424,4316.68)
TDI: U5.23 XP1.3 | length 441.1
  Top Layer w6: XP1.3 3298,4350.68 3310,4338.68 3550,4338.68 3615.94,4272.74 U5.23
TDO: U5.25 XP1.2 | length 466.6
  Top Layer w6: XP1.2 3248,4318.68 3274,4292.68 3550,4292.68 3576.57,4266.11 U5.25
TMS: U5.22 XP1.4 | length 399.3
  Top Layer w6: XP1.4 3348,4374.68 3366,4356.68 3556,4356.68 3635.62,4277.06 U5.22
VCC: C1.2 C2.2 CART1.1 D1.2 R1.2 R2.1 U2.14 U2.29 U2.43 U2.53 U4.6 U5.9 U5.13 U5.31 U5.45 U5.59 U5.63 U5.80 U5.94 XP1.1 | length 6487.4
  Top Layer w6: U4.6@4447.21,4142.43 4447.21,4173.89 4500,4226.68 4500,4292.68 4478,4314.68 C1.2@4472.44,4314.68
  Top Layer w8: v2(3463.17,4073.54) 3465.24,4071.48 U5.31 ; U5.59 v2@3734.05,3728.63 ; v2(4892.8,4360.68) U2.14
  Top Layer w10: v2@3457.74,3795.89 U5.45 3611.28,3795.89 v2(3612.44,3797.04) ; C2.2@3637.94,4337.12 3674.38,4300.68 3809.76,4300.68 ; v2(3812,3730.68) 3812.79,3729.89 U5.63 ; U5.13 3812.79,4297.65 3809.76,4300.68 ; R2.1@3889.94,4337.02 3891.53,4335.43 3891.53,4300.68 ; U5.9 3891.53,4300.68 ; v2(4050,3776.68) 4049.52,3776.2 U5.80 ; v2(4092,3644.68) 3994,3742.68 3994,3774.68 v2(3996,3776.68) 3997.39,3778.07 3997.39,3853.83 4042.17,3898.61 4042.17,4022.32 4071.64,4051.79 U5.94 ; v2(4474.6,4347.65) 4474.6,4318.83 4410.3,4318.83 4316.49,4225.03 4123.65,4225.03 4048,4300.68 3891.53,4300.68 ; v2(4596,3640.68) 4617.3,3640.68 U2.29@4617.3,3607.88 ; U2.43@4892.8,3615.88 4892.8,3579.88 v2(4904,3568.68) ; v2(5086,3568.68) 5089.7,3572.38 U2.53@5089.7,3615.88 ; 3809.76,4300.68 3891.53,4300.68
  Top Layer w24: v2(3340,3873.65) D1.2@3340,3905.73 ; C2.2@3637.94,4337.12 3700.18,4337.12 R1.2@3700.28,4337.02
  Top Layer w45: 3267.05,3379.32 3271.23,3383.5 v4(3271.23,3498.99)
  Bottom Layer w8: v2(4474.6,4347.65) 4487.63,4360.68 v2(4892.8,4360.68)
  Bottom Layer w10: v2(3612.44,3797.04) 3651.49,3797.04 3719.86,3728.68 v2(3734,3728.68) 3810,3728.68 v2(3812,3730.68) 3911.39,3730.68 3957.39,3776.68 v2(3996,3776.68) v2(4050,3776.68) ; v2(4092,3644.68) 4096,3640.68 v2(4596,3640.68) 4856,3640.68 4904,3592.68 v2(4904,3568.68) v2(5086,3568.68)
  Bottom Layer w18: XP1.1 3198,4302.68 3292,4208.68 3426,4208.68 3554,4336.68 v2(3670,4336.68)
  Bottom Layer w20: 3271.23,4068.54 3276.24,4073.54 v2(3463.17,4073.54)
  Bottom Layer w24: 3271.23,3873.65 v2(3340,3873.65) 3399.5,3873.65 3457.08,3816.07 3457.08,3796.55 v2(3457.17,3796.46)
  Bottom Layer w40: v4(3271.23,3498.99) 3271.23,3873.65 3271.23,4068.54 3271.23,4187.91 3292,4208.68
VMIX: C3.1 D1.1 D2.1 R4.2 U4.8 | length 1702.9
  Top Layer w8: D2.1@3274,3998.06 3340,3998.06 3372.8,3998.06 R4.2@3403.35,3967.5 ; R4.2@3406.51,3968.1 v2(3448,3968.1) ; U4.8@4407.84,4146.43 4407.84,4184.08 C3.1@4472.44,4248.68 ; v2(4432,4294.68) 4472.44,4254.24 C3.1
  Bottom Layer w10: v2(3448,3968.1) 3576,4096.1 3576,4118.68 3756,4298.68 3756,4340.68 3778,4362.68 3870,4362.68 3890,4342.68 3890,4242.68 3910,4222.68 4252,4222.68 4274,4244.68 4324,4244.68 4374,4294.68 v2(4432,4294.68)
~CS2~: CART1.30 R4.1 U4.30 U5.89 | length 2580.7
  Top Layer w6: U5.89 4149.31,3953.37 4165.58,3937.1 4165.58,3795.1 4220,3740.68 4290.68,3740.68 v1(4310.75,3720.6) ; v1(4582.5,3756.02) 4506.27,3679.8 4506.27,3636.91 4506.27,3556.29 4519.39,3543.17 4844.8,3543.17 4993.95,3394.03 CART1.30
  Top Layer w8: R4.1@3403.35,3908.18 3447.05,3908.18 v1(3447.97,3909.1)
  Bottom Layer w6: v1(3447.97,3909.1) 3496.1,3909.1 3555.87,3849.34 3555.87,3792.72 3680.53,3668.06 4201.88,3668.06 4254.42,3720.6 v1(4310.75,3720.6) 4425.62,3720.6 4446.39,3741.36 4565.58,3741.36 4580.24,3756.02 v1(4582.5,3756.02)
~CS~: CART1.5 U2.32 U5.50 | length 1672.2
  Top Layer w6: U5.50 3549.22,3697.46 3556,3690.68 v2(3556,3488.68) 3517.57,3450.25 CART1.5 ; v1(4676,3562.68) 4676.3,3562.98 U2.32@4676.3,3615.88
  Bottom Layer w6: v2(3556,3488.68) 4036,3488.68 4078.7,3445.98 4133.3,3445.98 4226,3538.68 4652,3538.68 v1(4676,3562.68)
~RD~: CART1.4 U2.34 U4.32 U5.49 | length 2083.3
  Top Layer w6: CART1.4 3458,3323.45 3458,3452.11 3418.7,3491.41 3418.7,3679.38 3456,3716.68 v1(3575.77,3716.68) ; U4.32@4545.64,3640.91 4545.64,3607.03 4566,3586.68 v1(4566,3562.68) ; U2.34@4715.7,3615.88 4715.7,3572.98 v1(4716,3572.68)
  Bottom Layer w6: v1(3575.77,3716.68) 3574.88,3716.68 3554.5,3696.3 3554.5,3552.45 3600.27,3506.68 4142,3506.68 4220,3584.68 4544,3584.68 v1(4566,3562.68) 4586,3582.68 4706,3582.68 v1(4716,3572.68)
~WR~: CART1.3 U2.13 U4.5 U5.48 | length 2683.4
  Top Layer w6: CART1.3 3399.46,3692.14 3443.8,3736.48 3589.8,3736.48 3634,3780.68 3634,3950.68 3663.17,3921.51 v1(3667.54,3921.51) ; U4.5@4466.9,4146.43 4466.9,4059.77 v1(4518,4008.68) ; v1(4912.51,4008.27) U2.13@4912.5,4395.48
  Bottom Layer w6: v1(3667.54,3921.51) 3692.28,3946.25 4372.62,3946.25 4389.24,3962.87 4445.03,3962.87 4490.84,4008.68 v1(4518,4008.68) 4912.1,4008.68 v1(4912.51,4008.27)
pads on no net: CART1.2 CART1.16 U2.16 U2.17 U2.27 U2.28 U2.30 U2.40 U2.55 U2.56 U4.31 U5.12 U5.14 U5.27 U5.28 U5.29 U5.30 U5.33 U5.34 U5.37 U5.38 U5.39 U5.40 U5.41 U5.42 U5.43 U5.44 U5.62 U5.64 U5.67 U5.73 U5.74 U5.75 U5.76 U5.77 U5.78 U5.81 U5.82 U5.83 U5.84 U5.85 U5.86 U5.87 U5.88
copper on no net: | length 1451.3
  Top Layer w6: 3889.82,3611.69 3892,3609.51 3892,3530.84 3949.01,3473.83 4090.84,3473.83 v1(4098,3466.68) 4167.18,3397.5 4167.18,3322.94 ; 4525.95,3640.91 4525.95,3568.72 v1(4530,3564.68) ; 4526,3642.96 4526,3680.68 4528.82,3683.5 v1(4616.54,3683.5) ; 4833.8,3615.88 4833.8,3682.48 v1(4834,3682.68)
  Bottom Layer w6: v1(4098,3466.68) 4130,3466.68 4218,3554.68 4520,3554.68 v1(4530,3564.68) ; v1(4616.54,3683.5) 4617.35,3682.68 v1(4834,3682.68)

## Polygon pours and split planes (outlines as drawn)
GND on Bottom Layer (solid, remove dead copper, pour order 2): 3037.24,3000 5459.24,3000 5459.24,4536 3037.24,4536
GND on Top Layer (solid, remove dead copper): 3000,3016.68 5444,3016.68 5444,4546.68 3000,4546.68

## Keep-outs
Top Layer:
  region: 3053,3115.99 5318.2,3115.99 5318.2,3420.68 3053,3420.68
  region: 3610.11,4354.68 3916,4354.68 3916,4378.5 3610.11,4378.5
  region: 4146,3734.68 4176,3734.68 4176,3771.21 4146,3771.21
  region: 4977,3628.68 5047,3628.68 5047,3648.68 4977,3648.68
  region: 3726,3572.68 3866,3572.68 3866,3602.68 3726,3602.68
  region: 4316.89,3581.68 4456.89,3581.68 4456.89,3611.68 4316.89,3611.68
  region: 5095,3402.68 5095,3542.68 5065,3542.68 5065,3402.68
  region: 3144,4279.52 3561.08,4279.52 3561.08,4300.68 3144,4300.68
  region: 3390,4364.34 3424.19,4364.34 3424.19,4453.68 3390,4453.68
  region: 4601.66,4414.68 5164.4,4414.68 5164.4,4444.68 4601.66,4444.68
  region: 3845.63,4198.91 3877.58,4198.91 3877.58,4271.66 3845.63,4271.66
  region: 4610,3596.11 5164.41,3596.11 5164.41,3626.11 4610,3626.11
  region: 3237.41,3864.43 3429.89,3864.43 3429.89,3995.12 3237.41,3995.12
  region: 4357.81,4167.65 4411.66,4167.65 4411.66,4190.04 4357.81,4190.04
  region: 4488.04,4232.82 4511.89,4232.82 4511.89,4337.73 4488.04,4337.73
  region: 4560.75,4168.18 4560.75,4233.61 4455.84,4233.61 4455.84,4168.18
  region: 3560.68,4175.53 3577.09,4175.53 3577.09,4227.89 3560.68,4227.89
Bottom Layer:
  region: 3410,4383.68 3410,4453.68 3390,4453.68 3390,4383.68
  region: 3586.57,3550.04 3586.57,3678.04 3566.57,3678.04 3566.57,3550.04
  region: 5029,3465.22 5060.35,3465.22 5060.35,3576.13 5029,3576.13
  region: 3419,4301.18 3165,4301.18 3165,4281.18 3419,4281.18
  region: 5076.58,4191.8 5107.68,4187.89 5127.47,4345.33 5096.36,4349.24
Board Outline Layer:
  lines w10: 3259.8,3193.51 3228,3225.31 3228,3520.68 3192.3,3520.68 3192.3,3665.33 3159.9,3690.65 3159.9,4454.37 4061.58,4454.37 4061.58,4358.88 ccw(c4194.93,4382.54) 4327.61,4355.38 4327.61,4454.37 5229.31,4454.37 5233,4450.68 5233,3685.4 5202.83,3664.54 5202.83,3519.73 5167.13,3519.73 5167.13,3225.88 ; 3260.14,3193.51 5134.89,3193.51 ; 5135.33,3193.51 5167.13,3225.31
Multi-Layer:
  region: 4383,4286.15 4383,4299.56 4301,4299.56 4301,4286.15

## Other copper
Top Layer:
  drawing of 409 lines, arcs and shapes, not listed
Bottom Layer:
  drawing of 171 lines, arcs and shapes, not listed

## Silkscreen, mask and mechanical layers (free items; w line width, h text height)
Top Silkscreen Layer:
  lines w5.91: 3228,3515.68 5167.13,3515.68 5167.13,3520.75 3228,3520.75 3228,3515.68
  text "TDI" at 3313.57,4300.58 h35 r90
  text "TDO" at 3266.1,4285.58 h35 r90
  text "TMS" at 3366.1,4285.58 h35 r90
  text "TCK" at 3418.37,4286.48 h35 r90
  text "GND" at 3469.65,4286.48 h35 r90
  text "VCC" at 3215.1,4283.58 h35 r90
  text "BAT-" at 3958,4278.68 h35
  text "BAT-" at 3234,3776.68 h35
  text "BAT+" at 3394,3642.68 h35
  text "Designed by Bread&Firseve" at 4006.93,3472.68 h35
  text "Lite Rev0.1" at 3781.72,3440.68 h35
  text "ChisFlash                F32S128V01" at 3423,3430.68 h78.74
  text "Layout by Mori" at 4006.93,3429.18 h35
